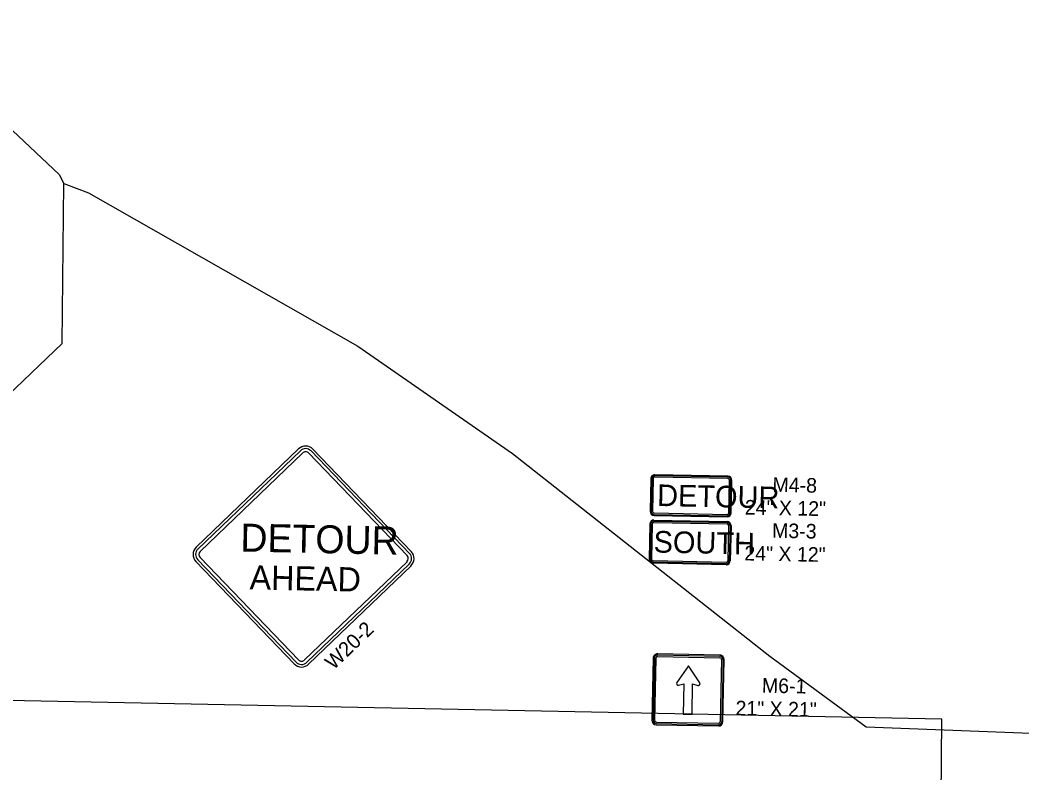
# Model space of a CAD drawing. Extents: x 331323 to 388339, y 121519 to 205315.
# Drawn here: x 371668 to 375372, y 131903 to 134687 of the extents above; entities that cross this region are included whole.
import ezdxf

# ---------------------------------------------------------------- set-up
doc = ezdxf.new("R2010")
doc.units = 0
for name, color, linetype in [('Level 21', 7, 'Continuous'), ('Level 57', 7, 'Continuous'), ('P_SGN_Cell', 7, 'Continuous')]:
    doc.layers.add(name, color=color, linetype=linetype)

msp = doc.modelspace()

# ---------------------------------------------------------------- linework, layer by layer
at = {"layer": 'Level 21'}
msp.add_lwpolyline([(387110, 131789), (379629.8, 131947), (379608.6, 129130.6), (378253.9, 129142.3), (378276.4, 129801.4), (377067.3, 129844.4), (377063.5, 130597.8), (375063.3, 130636.2), (375076, 132102.1), (370942.7, 132184.5)], dxfattribs=at)
at = {"layer": 'Level 57'}
for points in [[(366907.1, 140244.2), (366940.2, 140210.6), (366955.4, 140052.1), (366988.1, 139985.1), (367035.4, 139684.7), (367213.5, 139108.1), (367236.6, 138899.5), (367318.2, 138698.8), (367417, 138556.2), (367681.2, 138270.5), (367771.2, 138086.3), (367834.3, 137694.1), (367933.8, 137626.5), (368233.7, 137590.5), (368324.8, 137523), (368390.2, 137380.7), (368778.5, 136985.5), (369580.4, 136219.9), (370688.4, 135176.5), (371812.8, 134116.3), (371829.2, 134082.8)], [(371192.7, 132888.6), (371823.7, 133491.2), (371829.2, 134082.8)], [(371829.2, 134082.8), (371920.6, 134048.7), (372916.1, 133481.3), (373487.9, 133084.4), (374440.1, 132334.1), (374796.3, 132072.6), (378189.4, 131941.9)]]:
    msp.add_lwpolyline(points, dxfattribs=at)
at = {"layer": 'P_SGN_Cell'}
for p, q in [((374011.5, 132838.2), (374281.7, 132832.8)), ((374011.6, 132834.5), (374281.6, 132829)), ((373996.4, 132823.5), (373993.8, 132693.6)), ((374000.2, 132823.5), (373997.5, 132693.5)), ((374005.2, 132823.4), (374002.5, 132693.4)), ((374011.5, 132829.5), (374281.5, 132824)), ((374287.6, 132817.7), (374285, 132687.7)), ((374292.6, 132817.6), (374290, 132687.6)), ((374296.4, 132817.5), (374293.7, 132687.5)), ((374278.6, 132681.6), (374008.7, 132687)), ((374278.4, 132672.8), (374008.5, 132678.3)), ((374278.5, 132676.6), (374008.6, 132682)), ((374008.6, 132327.3), (374004, 132097.7)), ((374013, 132327.2), (374008.3, 132097.6)), ((374018.4, 132327.1), (374013.8, 132097.5)), ((374025.1, 132333.5), (374254.8, 132328.9)), ((374025.2, 132339), (374254.9, 132334.4)), ((374254.9, 132338.8), (374025.3, 132343.4)), ((374261.2, 132322.2), (374256.6, 132092.6)), ((374266.7, 132322.1), (374262, 132092.5)), ((374266.4, 132092.4), (374271, 132322)), ((374139.3, 132298.4), (374095.4, 132237.4)), ((374180.6, 132235.7), (374139.3, 132298.4)), ((374102.5, 132227.2), (374121.5, 132232.6)), ((374121.5, 132232.6), (374119.3, 132120.5)), ((374152.1, 132119.8), (374154.3, 132231.9)), ((374154.3, 132231.9), (374173.1, 132225.8)), ((374020.2, 132090.8), (374249.9, 132086.2)), ((374119.3, 132120.5), (374152.1, 132119.8)), ((374020, 132080.9), (374249.7, 132076.3)), ((374020.1, 132085.3), (374249.8, 132080.7))]:
    msp.add_line(p, q, dxfattribs=at)
for points in [[(372697.5, 133101.1), (372318.9, 132737.5)], [(372704.1, 133094.3), (372325.5, 132730.6)], [(373107.3, 132714.8), (372743.7, 133093.5)], [(373114.2, 132721.4), (372750.5, 133100.1)], [(372712.4, 133085.7), (372333.7, 132722)], [(373098.8, 132706.6), (372735.1, 133085.2)], [(373999.5, 132990.7), (373997.1, 132870.7)], [(374003.3, 132990.6), (374000.9, 132870.6)], [(374008.3, 132990.5), (374005.9, 132870.5)], [(374284.6, 132991.2), (374014.7, 132996.6)], [(374284.8, 132999.9), (374014.8, 133005.4)], [(374284.7, 132996.2), (374014.8, 133001.6)], [(374288.3, 132864.8), (374290.7, 132984.8)], [(374293.3, 132864.7), (374295.7, 132984.7)], [(374297.1, 132864.7), (374299.5, 132984.6)], [(374011.8, 132855.4), (374281.8, 132850)], [(374011.9, 132859.1), (374281.8, 132853.7)], [(374012, 132864.1), (374281.9, 132858.7)], [(372317.8, 132684.4), (372681.5, 132305.8)], [(372324.7, 132691), (372688.4, 132312.4)], [(372333.3, 132699.3), (372697, 132320.6)], [(372720, 132320.5), (373098.5, 132684)], [(372728.2, 132311.9), (373106.7, 132675.4)], [(372734.8, 132305), (373113.3, 132668.6)]]:
    msp.add_lwpolyline(points, dxfattribs=at)
for centre, radius, start, end in [((372723.5, 133074.1), 37.5, 43.8449, 133.8468), ((372723.5, 133074.1), 28, 43.8449, 133.8468), ((372723.5, 133074.1), 16.1, 43.8449, 133.8468), ((374014.5, 132990.4), 15, 88.8468, 178.8468), ((374014.5, 132990.4), 11.2, 88.8468, 178.8468), ((374014.5, 132990.4), 6.25, 88.8468, 178.8468), ((374014.5, 132990.4), 6.25, 88.8468, 96.1883), ((374284.5, 132984.9), 6.25, 358.8468, 88.8468), ((374284.5, 132984.9), 11.2, 358.8468, 88.8468), ((374284.5, 132984.9), 15, 358.8468, 88.8468), ((374012.1, 132870.4), 15, 178.8468, 268.8468), ((374012.1, 132870.4), 11.2, 178.8468, 268.8468), ((374012.1, 132870.4), 6.25, 178.8468, 268.8468), ((374011.4, 132823.2), 15, 89.6119, 178.8462), ((374011.4, 132823.2), 11.2, 88.8462, 178.8462), ((374281.4, 132817.8), 15, 358.8462, 88.8462), ((374282.1, 132865), 15, 268.8468, 358.8468), ((374282.1, 132865), 11.2, 268.8468, 358.8468), ((374282.1, 132865), 6.25, 268.8468, 358.8468), ((374011.4, 132823.2), 6.25, 88.8462, 178.8462), ((374281.4, 132817.8), 6.25, 358.8462, 88.8462), ((374281.4, 132817.8), 11.2, 358.8462, 88.8462), ((372344.9, 132710.4), 37.5, 133.8468, 223.8468), ((372344.9, 132710.4), 28, 133.8468, 223.8468), ((372344.9, 132710.4), 16.1, 133.8468, 223.8468), ((373087.2, 132695.5), 37.5, 313.8468, 43.8468), ((373087.2, 132695.5), 16.1, 313.8468, 43.8468), ((373087.2, 132695.5), 28, 313.8468, 43.8468), ((374008.8, 132693.3), 15, 178.8462, 268.8462), ((374008.8, 132693.3), 11.2, 178.8462, 268.8462), ((374008.8, 132693.3), 6.25, 178.8462, 268.8462), ((374278.7, 132687.8), 15, 268.8462, 358.8462), ((374278.7, 132687.8), 11.2, 268.8462, 358.8462), ((374278.7, 132687.8), 6.25, 268.8462, 358.8462), ((372708.5, 132331.8), 28, 223.854, 314.4977), ((372708.5, 132331.8), 16.1, 223.854, 314.4977), ((374025, 132327), 16.4, 88.8468, 178.8468), ((374025, 132327), 12, 88.8468, 178.8468), ((374025, 132327), 6.56, 88.8468, 178.8468), ((374254.6, 132322.4), 6.56, 358.8468, 88.8468), ((374254.6, 132322.4), 16.4, 59.4503, 88.8468), ((374254.6, 132322.4), 16.4, 358.8468, 88.8468), ((374254.6, 132322.4), 12, 358.8468, 88.8468), ((372708.5, 132331.8), 37.5, 223.854, 314.4977), ((374100.8, 132233.6), 6.56, 144.3172, 285.6494), ((374175.1, 132232.1), 6.56, 252.0442, 33.3765), ((374020.4, 132097.3), 16.4, 178.8468, 268.8468), ((374020.4, 132097.3), 12, 178.8468, 268.8468), ((374020.4, 132097.3), 6.56, 178.8468, 268.8468), ((374250, 132092.7), 16.4, 268.8468, 358.8468), ((374250, 132092.7), 12, 268.8468, 358.8468), ((374250, 132092.7), 6.56, 268.8468, 358.8468)]:
    msp.add_arc(centre, radius, start, end, dxfattribs=at)

# ---------------------------------------------------------------- texts
for s, height, rotation, p in [('M4-8', 54, 358.8468, (374449.2, 132942.3)), ('DETOUR', 80, 358.8468, (374022.6, 132890)), ('24" X 12"', 54, 358.8468, (374346.8, 132858.6)), ('DETOUR', 103.57, 358.8468, (372481.7, 132721.7)), ('SOUTH', 80, 358.8462, (374009.5, 132718)), ('M3-3', 54, 358.8462, (374447.6, 132772.6)), ('24" X 12"', 54, 358.8462, (374345.2, 132688.9)), ('AHEAD', 89.29, 358.8468, (372515.8, 132581.5)), ('W20-2', 54, 43.8468, (372826.7, 132281.3)), ('M6-1', 54, 358.8468, (374410.1, 132199.6)), ('21" X 21"', 54, 358.8468, (374312.5, 132115.8))]:
    msp.add_text(s, height=height, rotation=rotation, dxfattribs=at).set_placement(p)

doc.saveas('drawing.dxf')
